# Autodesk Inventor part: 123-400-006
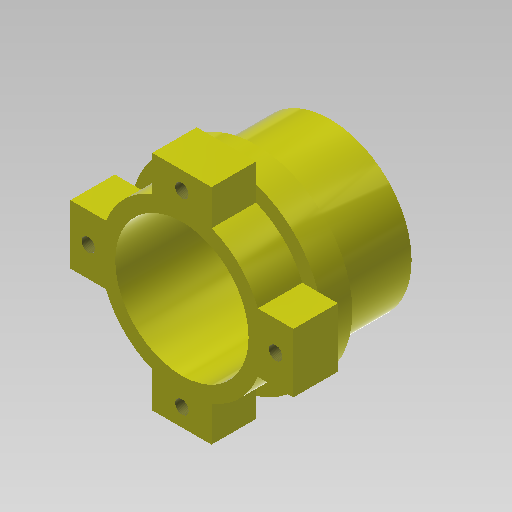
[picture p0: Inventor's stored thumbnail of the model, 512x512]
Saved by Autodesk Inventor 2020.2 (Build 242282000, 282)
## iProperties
Created: 2006-08
Part Number: 123-400-006
Material: Aluminium-6061
Document SubType Name: Modeling
Designer: F.Stasiak
Description: Głowica
Mass: 164964 g
Surface Area: 22444.5 cm^2
Volume: 60872.1 cm^3
Density: 2.71 g/cm^3
Appearance: Gładkie — żółte
Manager: www.cadconsulting.pl
Company: Fabian Stasiak CAD Consulting
KODMAT: 13-1654
Author: F.Stasiak
Subject: Zbiór ćwiczeń. Autodesk Inventor 2020. Kurs podstawowy
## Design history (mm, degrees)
sketch "Szkic1"
  geometry: C1 r 325 at (0, 0); C2 r 275 at (0, 0); 1 further point
  constraints: 2 centre point, 2 coincident
  dimensions: "d0" = 650 diameter of C1; "d1" = 550 diameter of C2
extrude "Wyciągnięcie proste1" new body sketch "Szkic1" distance "d2" = 100; taper "d3" = 0 deg
extrude "Wyciągnięcie proste2" join sketch "Szkic1" stored distance "d4" = 500; taper "d5" = 0 deg
sketch "Szkic2"
  geometry: C1 r 275 at (0, 0) reference; C2 r 225 at (0, 0)
  constraints: 1 centre point, 1 coincident
  dimensions: "d6" = 450 diameter of C2
extrude "Wyciągnięcie proste3" cut sketch "Szkic2" extent not by distance; stored distance "d7" = 500; taper "d8" = 0 deg
sketch "Szkic3"
  geometry: L1 (-100, 256.174)-(-100, 376.174); L2 (-100, 376.174)-(100, 376.174); L3 (100, 376.174)-(100, 256.174); L4 (0, 376.174)-(0, 0); A1 r 275 centre (0, 0) between (-100, 256.174) and (100, 256.174) reference
  constraints: 8 end point, 2 parallel, 2 point on circle, 1 midpoint, 1 perpendicular, 1 vertical
  dimensions: "d9" = 200 distance of L1.end L2.end; "d10" = 120 distance of L2.end L3.end
extrude "Wyciągnięcie proste4" join sketch "Szkic3" stored distance "d11" = 500; taper "d12" = 0 deg
sketch "Szkic4"
  geometry: L1 (-100, 376.174)-(-100, 256.174) reference; L2 (100, 256.174)-(100, 376.174) reference; L3 (-100, 316.174)-(100, 316.174); 1 further point
  constraints: 3 midpoint, 2 end point
hole "Otwór1" sketch "Szkic4" at (0, 316.174) diameter "d16" = 45.67; stored, may be unused: countersink angle "d20" = 90 deg, drill point angle "d22" = 118 deg; dims "d17" = 6, "d18" = 4, "d19" = 2, "d21" = 100
pattern_circular "Szyk kołowy1" dims angle "d14" = 360 deg
sketch "Szkic5"
  geometry: 6 further points
hole "Otwór2" sketch "Szkic5" at (0, 250), (-216.506, 125), (-216.506, -125), (0, -250), (216.506, -125), (216.506, 125) diameter "d23" = 11.835; stored, may be unused: countersink angle "d27" = 90 deg, drill point angle "d29" = 120 deg; dims "d24" = 25, "d25" = 4, "d26" = 2, "d28" = 30
sketch "Szkic6"
  geometry: 6 further points
node "Bryła1"
node "Korpusy bryłowe"
node "Korpusy powierzchniowe"
